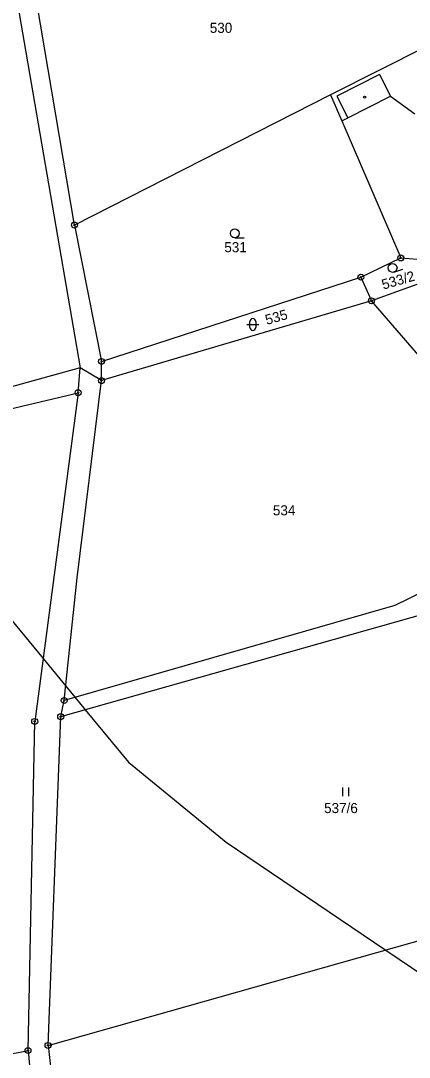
# Model space of a CAD drawing. Extents: x -547623 to -538651, y -1096714 to -1086522.
# Drawn here: x -544697.7 to -544632.1, y -1093361.8 to -1093186.7 of the extents above; entities that cross this region are included whole.
import ezdxf

# ---------------------------------------------------------------- set-up
doc = ezdxf.new("R2010")
doc.units = 0
for name, color, linetype in [('Vrstva 1', 7, 'Continuous'), ('Vrstva 25', 7, 'Continuous'), ('Vrstva 33', 7, 'Continuous'), ('Vrstva 52', 7, 'Continuous'), ('Vrstva 83', 7, 'Continuous'), ('Vrstva 86', 7, 'Continuous')]:
    doc.layers.add(name, color=color, linetype=linetype)

msp = doc.modelspace()

# ---------------------------------------------------------------- linework, layer by layer
at = {"layer": 'Vrstva 1'}
for points in [[(-544704.24, -1093149.12), (-544687.66, -1093245.35)], [(-544688.6, -1093221.24), (-544699.41, -1093157.27)], [(-544621.18, -1093187), (-544645.38, -1093199.23)], [(-544645.38, -1093199.23), (-544688.6, -1093221.24)], [(-544645.38, -1093199.23), (-544643.49, -1093203.64)], [(-544642.48, -1093203.14), (-544635.27, -1093199.46)], [(-544635.27, -1093199.46), (-544631.18, -1093202.47)], [(-544643.49, -1093203.64), (-544642.48, -1093203.14)], [(-544643.49, -1093203.64), (-544633.55, -1093226.8)], [(-544688.6, -1093221.24), (-544684.04, -1093244.28)], [(-544640.28, -1093230.05), (-544633.55, -1093226.8)], [(-544633.55, -1093226.8), (-544627.93, -1093227.24)], [(-544684.04, -1093244.28), (-544640.28, -1093230.05)], [(-544640.28, -1093230.05), (-544638.5, -1093234.03)], [(-544630.81, -1093231.29), (-544638.5, -1093234.03)], [(-544638.5, -1093234.03), (-544684.04, -1093247.53)], [(-544605.97, -1093271.64), (-544638.5, -1093234.03)], [(-544684.04, -1093247.53), (-544684.04, -1093244.28)], [(-544687.66, -1093245.35), (-544734.43, -1093258.29)], [(-544687.99, -1093249.56), (-544687.66, -1093245.35)], [(-544684.04, -1093247.53), (-544687.66, -1093245.35)], [(-544688.14, -1093280.85), (-544684.04, -1093247.53)], [(-544733.65, -1093260.4), (-544687.99, -1093249.56)], [(-544687.99, -1093249.56), (-544695.31, -1093305.1)], [(-544609.47, -1093273.22), (-544634.53, -1093285.49)], [(-544690.33, -1093301.58), (-544688.14, -1093280.85)], [(-544690.92, -1093304.29), (-544621.44, -1093284.64)], [(-544634.53, -1093285.49), (-544690.33, -1093301.58)], [(-544690.92, -1093304.29), (-544690.33, -1093301.58)], [(-544696.44, -1093360.69), (-544695.31, -1093305.1)], [(-544693.06, -1093359.84), (-544690.92, -1093304.29)], [(-544693.06, -1093359.84), (-544623.05, -1093340.04)], [(-544693.06, -1093359.84), (-544686.74, -1093416.04)], [(-544802.11, -1093381.56), (-544696.44, -1093360.69)], [(-544696.44, -1093360.69), (-544691.36, -1093417.51)]]:
    msp.add_lwpolyline(points, dxfattribs=at)
at = {"layer": 'Vrstva 25'}
for p, q in [((-544661.55, -1093223.39), (-544659.95, -1093223.39)), ((-544634.71, -1093229.2), (-544633.18, -1093228.72)), ((-544659.51, -1093238.04), (-544657.51, -1093238.04)), ((-544659.01, -1093238.54), (-544659.01, -1093237.54)), ((-544658.01, -1093237.54), (-544658.01, -1093238.54)), ((-544643.31, -1093317.74), (-544643.31, -1093316.24)), ((-544642.31, -1093317.74), (-544642.31, -1093316.24))]:
    msp.add_line(p, q, dxfattribs=at)
for centre, radius in [((-544639.64, -1093199.64), 0.175), ((-544661.55, -1093222.64), 0.75), ((-544634.93, -1093228.48), 0.75)]:
    msp.add_circle(centre, radius, dxfattribs=at)
for centre, start, end in [((-544658.51, -1093237.54), 0, 180), ((-544658.51, -1093238.54), 180, 0)]:
    msp.add_arc(centre, 0.5, start, end, dxfattribs=at)
at = {"layer": 'Vrstva 33'}
for points in [[(-544637.13, -1093195.81), (-544644.35, -1093199.49)], [(-544637.13, -1093195.81), (-544635.27, -1093199.46)], [(-544644.35, -1093199.49), (-544642.48, -1093203.14)]]:
    msp.add_lwpolyline(points, dxfattribs=at)
at = {"layer": 'Vrstva 52'}
msp.add_lwpolyline([(-544756.77, -1093160.09), (-544744, -1093222), (-544730.5, -1093250), (-544725.67, -1093255.87), (-544723.86, -1093258.08), (-544693.91, -1093294.48), (-544690.07, -1093299.15), (-544688.5, -1093301.05), (-544686.8, -1093303.12), (-544679.5, -1093312), (-544663, -1093325.5), (-544636.09, -1093343.73), (-544616.5, -1093357), (-544595.41, -1093385.12)], dxfattribs=at)
at = {"layer": 'Vrstva 83'}
for centre, radius in [((-544688.6, -1093221.24), 0.5), ((-544688.6, -1093221.24), 0.1), ((-544633.55, -1093226.8), 0.5), ((-544633.55, -1093226.8), 0.1), ((-544640.28, -1093230.05), 0.5), ((-544640.28, -1093230.05), 0.1), ((-544638.5, -1093234.03), 0.5), ((-544638.5, -1093234.03), 0.1), ((-544684.04, -1093244.28), 0.5), ((-544684.04, -1093244.28), 0.1), ((-544684.04, -1093247.53), 0.5), ((-544684.04, -1093247.53), 0.1), ((-544687.99, -1093249.56), 0.5), ((-544687.99, -1093249.56), 0.1), ((-544690.33, -1093301.58), 0.5), ((-544690.33, -1093301.58), 0.1), ((-544690.92, -1093304.29), 0.5), ((-544695.31, -1093305.1), 0.5), ((-544695.31, -1093305.1), 0.1), ((-544690.92, -1093304.29), 0.1), ((-544693.06, -1093359.84), 0.5), ((-544693.06, -1093359.84), 0.1), ((-544696.44, -1093360.69), 0.5), ((-544696.44, -1093360.69), 0.1)]:
    msp.add_circle(centre, radius, dxfattribs=at)

# ---------------------------------------------------------------- texts
at = {"layer": 'Vrstva 86'}
for s, p in [('530', (-544665.77, -1093188.77)), ('531', (-544663.32, -1093225.83)), ('534', (-544655.12, -1093270.28)), ('537/6', (-544646.48, -1093320.59))]:
    msp.add_text(s, height=1.7, dxfattribs=at).set_placement(p)
for s, rotation, p in [('533/2', 16.1816, (-544636.48, -1093232.16)), ('535', 15.933, (-544656.14, -1093238.12))]:
    msp.add_text(s, height=1.7, rotation=rotation, dxfattribs=at).set_placement(p)

doc.saveas('drawing.dxf')
